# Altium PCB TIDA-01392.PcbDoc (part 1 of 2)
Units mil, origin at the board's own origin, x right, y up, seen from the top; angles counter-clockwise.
Board outline 1055.12 x 1877.5 mil, 6 copper layers (Layer 1 - Top Layer, Layer 2 - GND, Layer 3 - Signal, Layer 4 - Signal, Layer 5 - PWR, Layer 6 - Bottom Layer), stack 66.234 mil thick; 89 components, 55 nets, 288 pads, 112 vias.
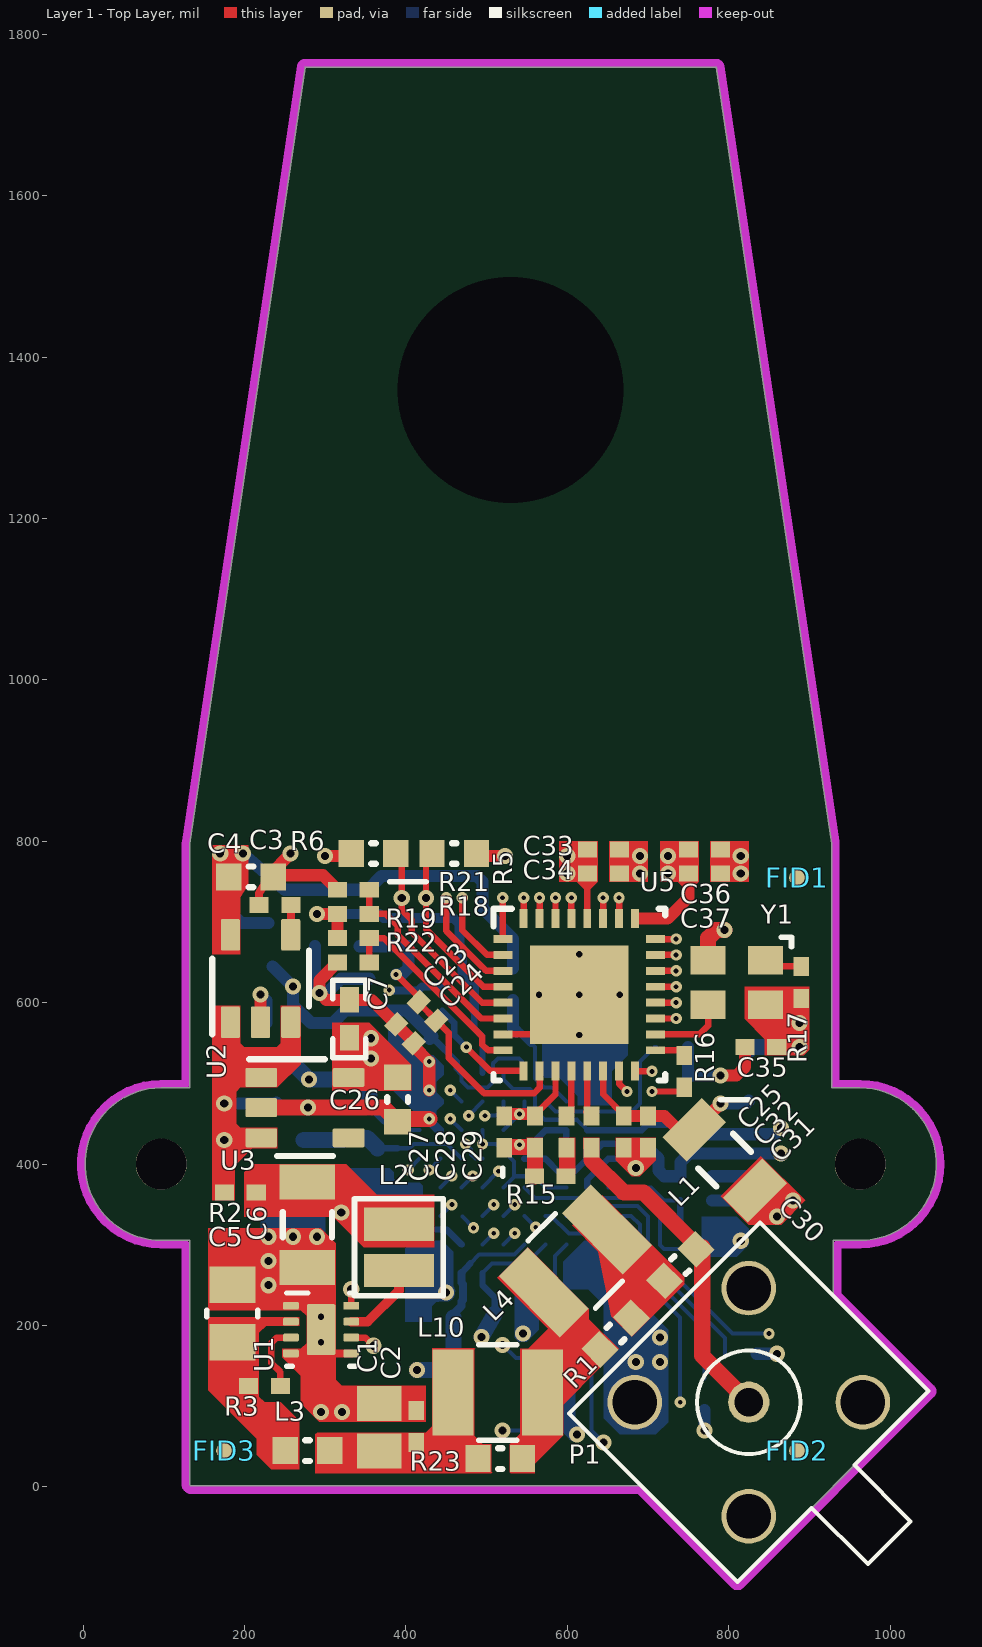
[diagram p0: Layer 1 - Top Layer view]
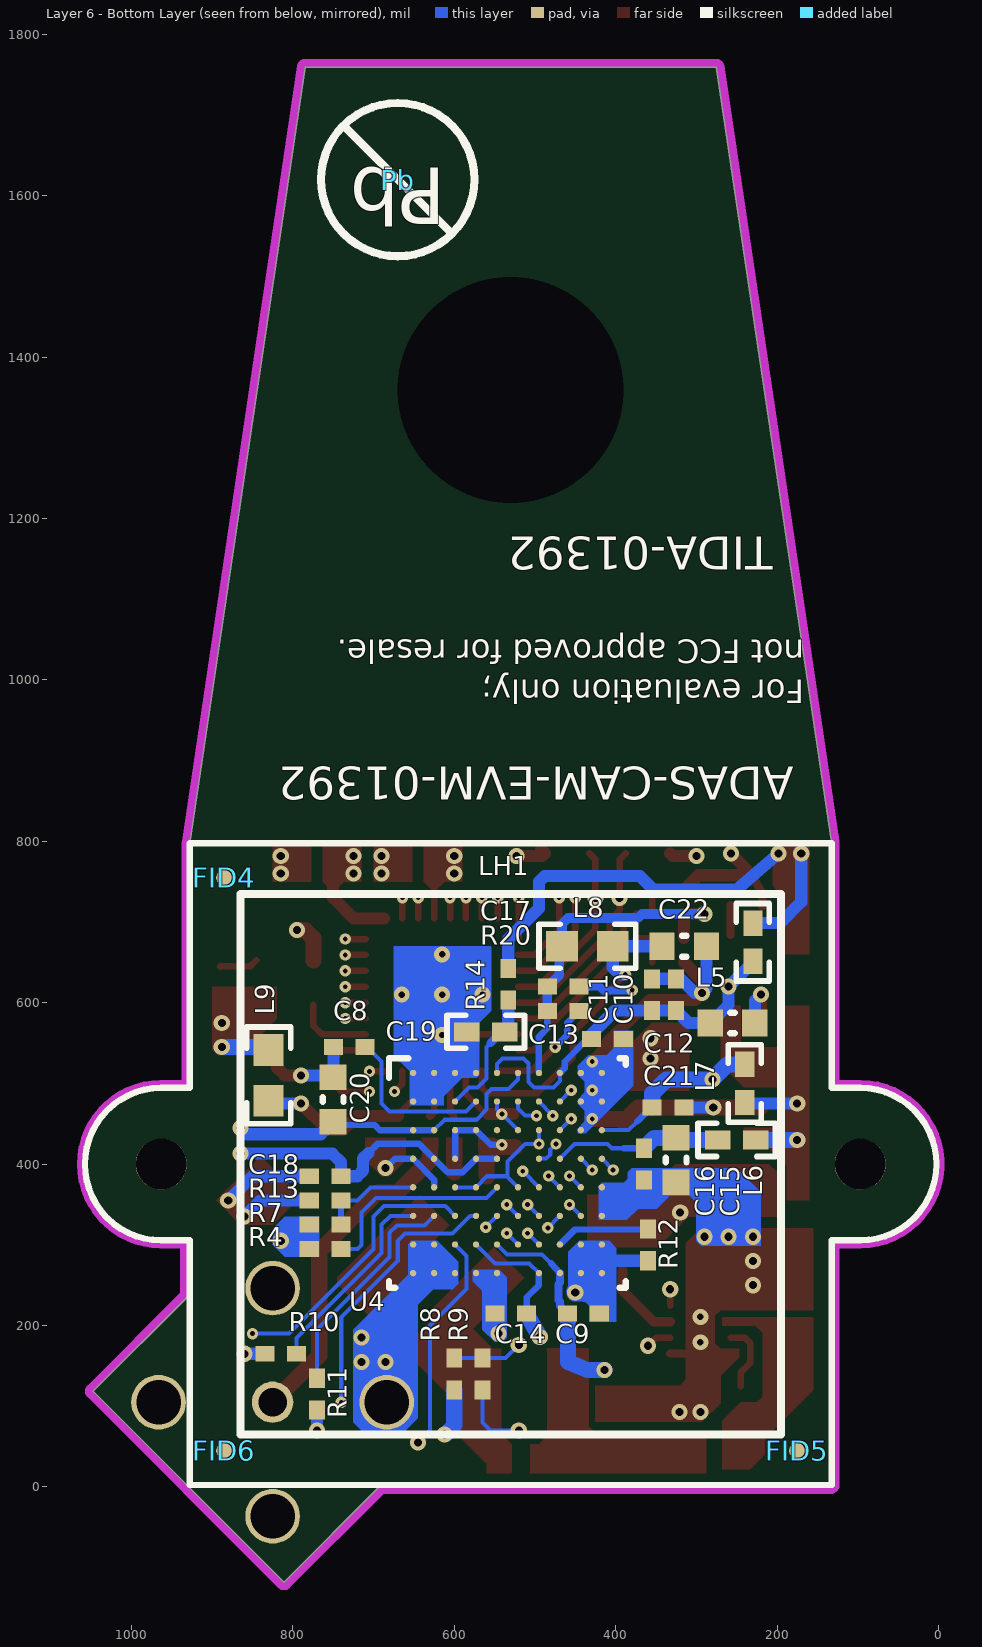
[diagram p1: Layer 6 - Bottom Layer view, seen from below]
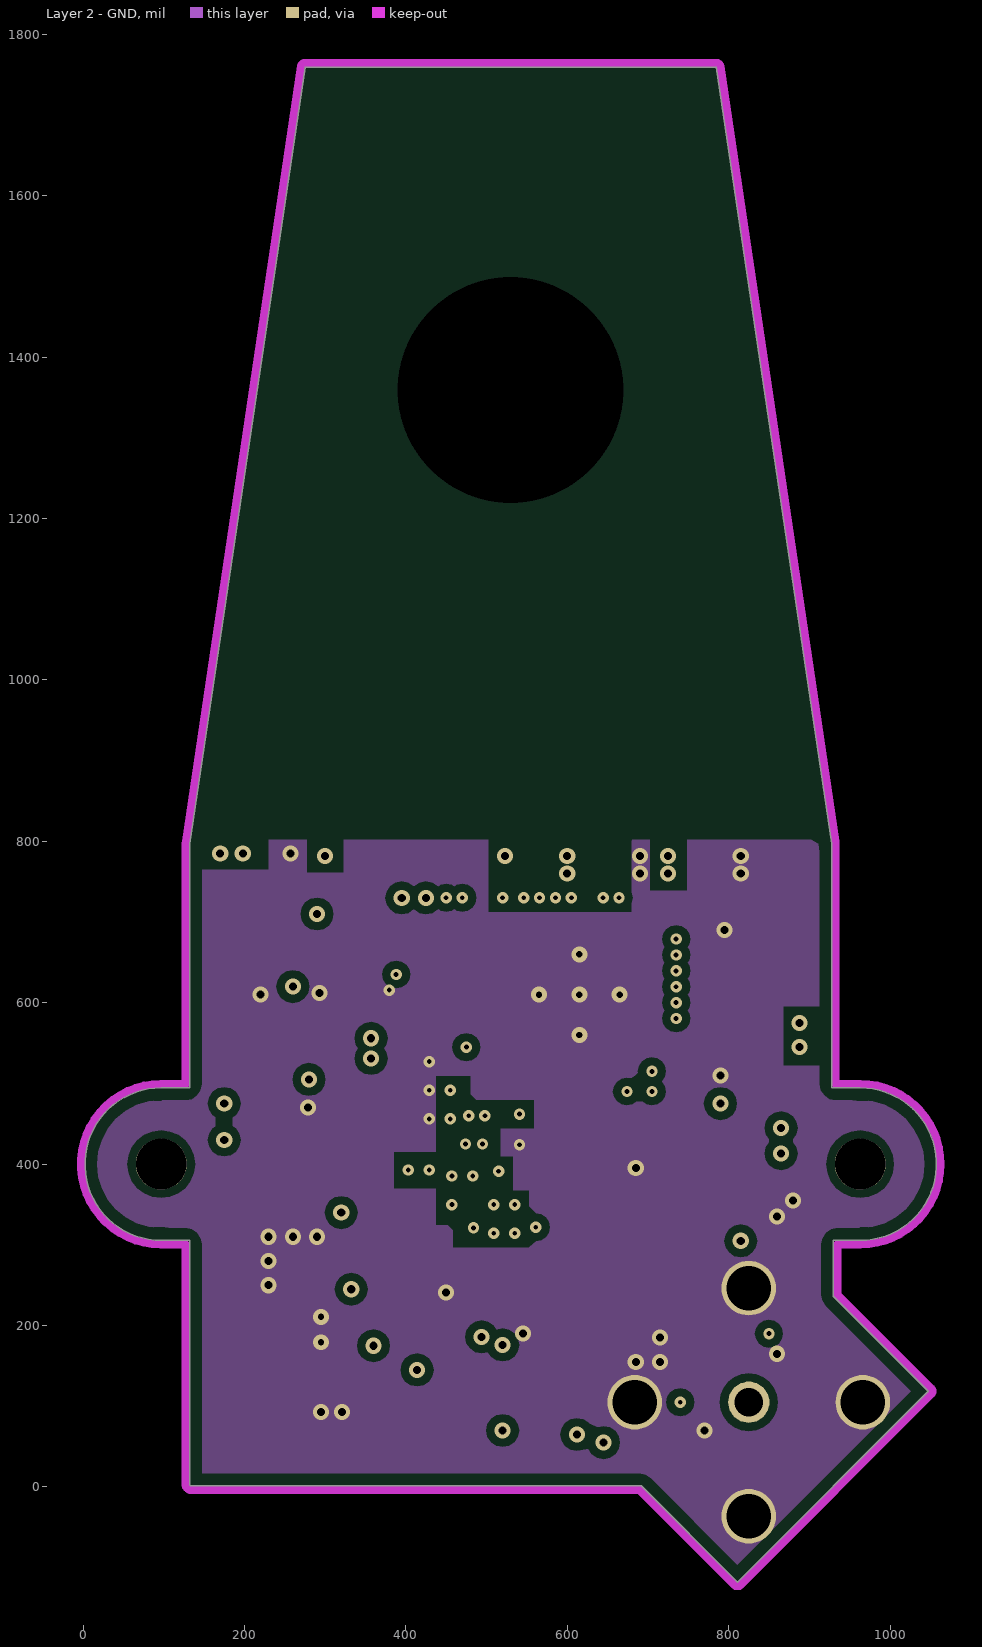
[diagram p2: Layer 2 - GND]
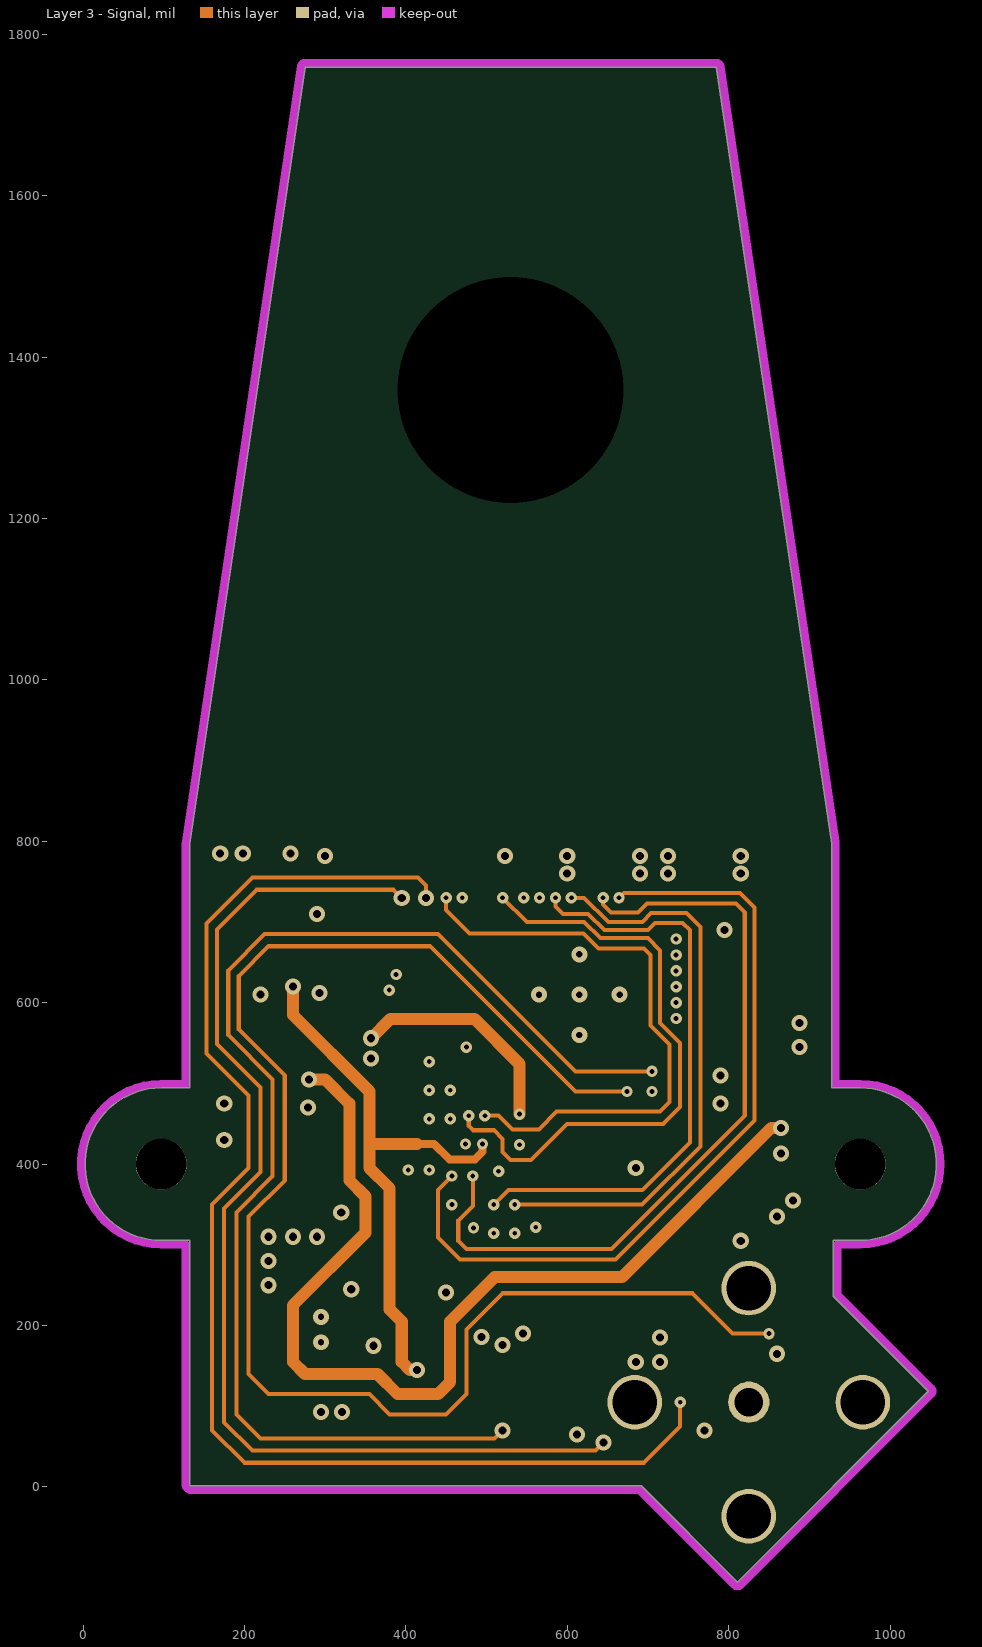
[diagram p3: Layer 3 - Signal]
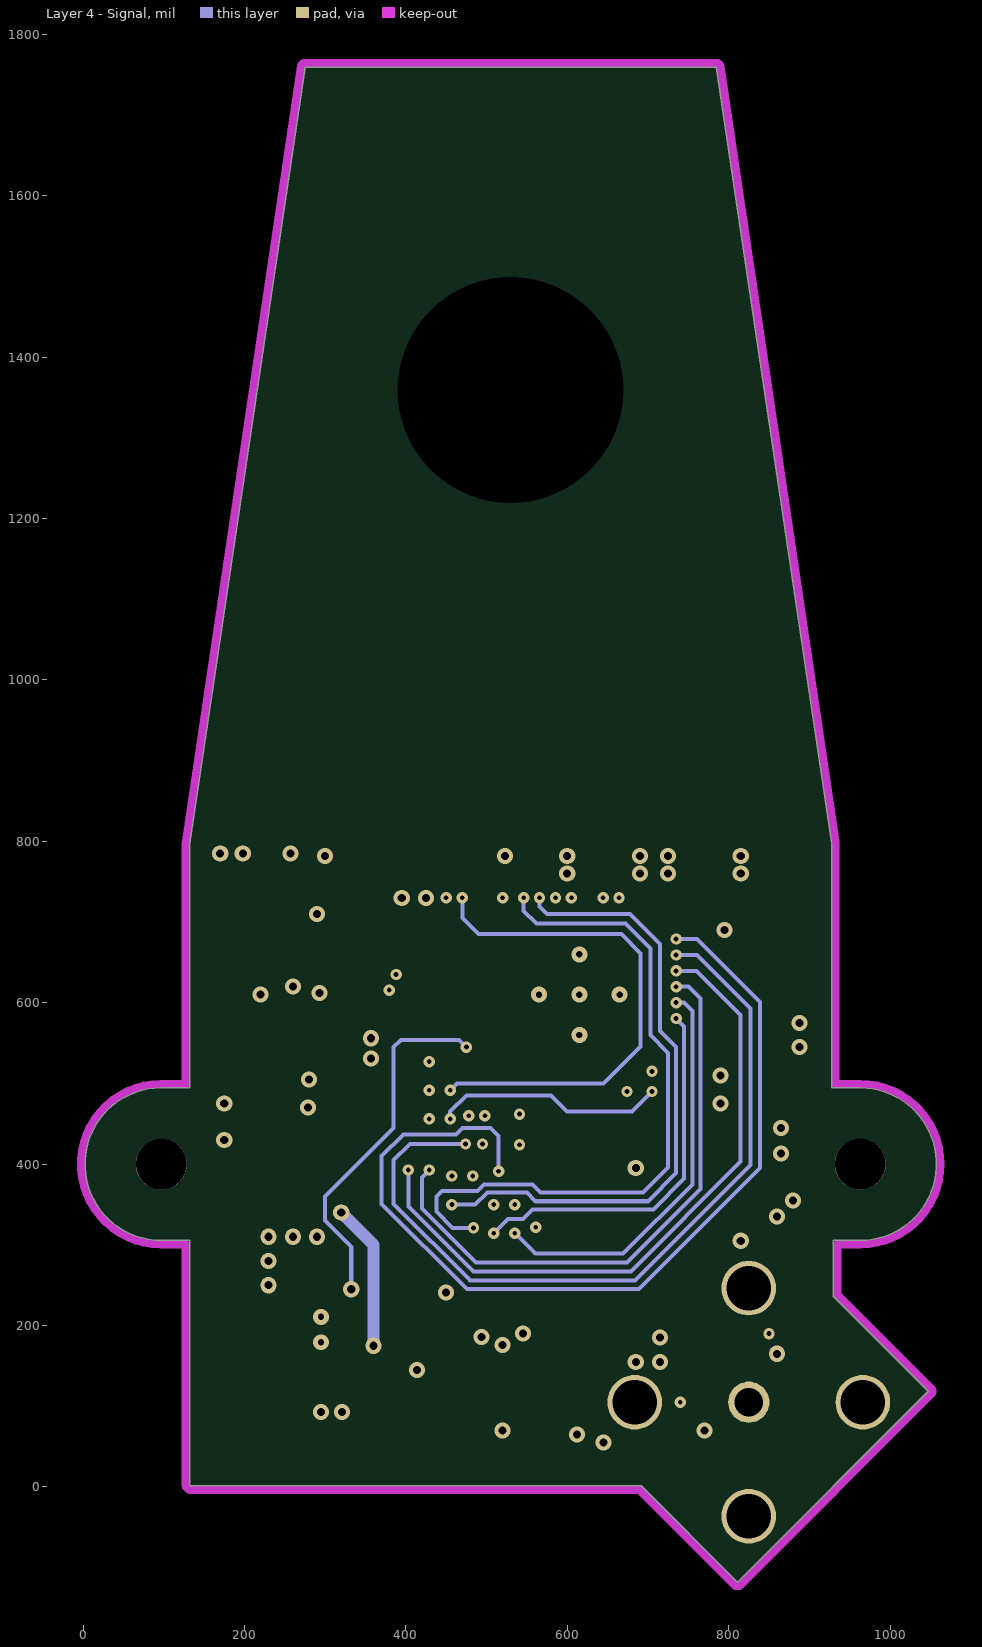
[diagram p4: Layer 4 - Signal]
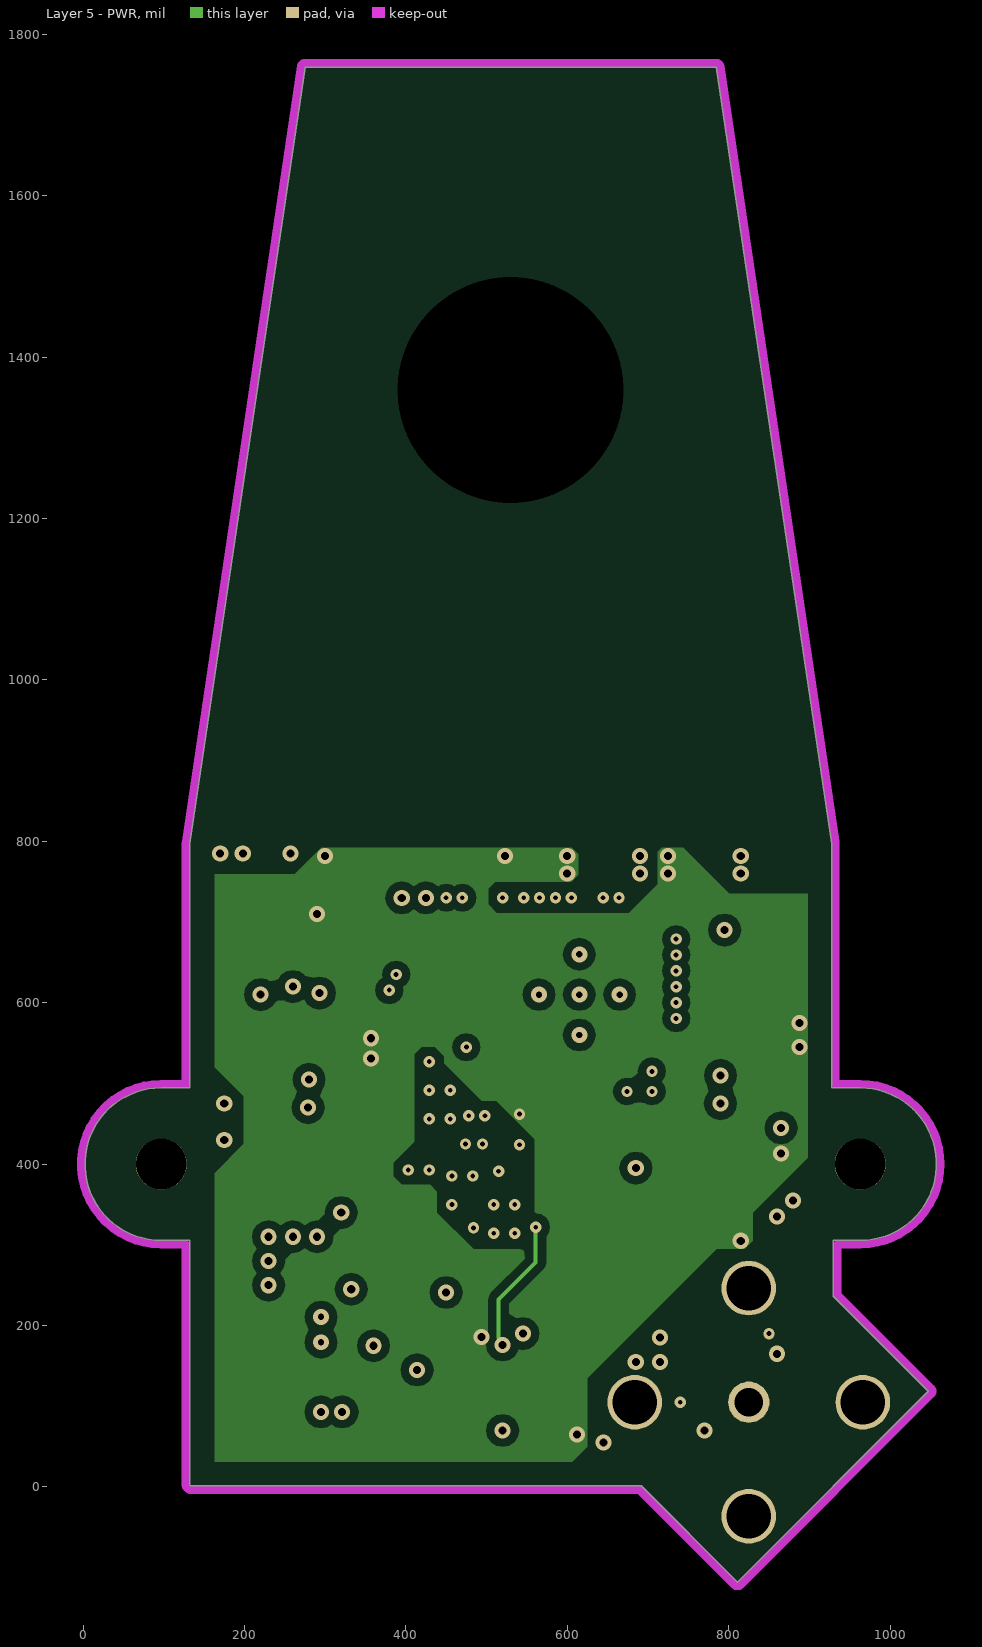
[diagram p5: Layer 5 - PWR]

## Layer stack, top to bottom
Top Solder: solder mask 0.4, Solder Resist, Dk 3.5
Layer 1 - Top Layer: signal copper 1.4
Dielectric 1: prepreg 12.6, 370HR, Dk 4.2
Layer 2 - GND: signal copper 1.4
Dielectric 2: core 8, 370HR, Dk 4.2
Layer 3 - Signal: signal copper 1.417
Dielectric 3: prepreg 16.6, 370HR, Dk 4.2
Layer 4 - Signal: signal copper 1.417
Dielectric 4: core 8, 370HR, Dk 4.2
Layer 5 - PWR: signal copper 1.4
Dielectric 5: prepreg 12.6, 370HR, Dk 4.2
Layer 6 - Bottom Layer: signal copper 1.4
Bottom Solder: solder mask 0.4, Solder Resist, Dk 3.5

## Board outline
96.93,305.51 132.36,305.51 132.36,2.36 133.35,1.37 691.63,1.37 811,-118 1047.5,118.5 929.63,236.37 929.63,305.51 963.07,305.51 ccw(c963.07,400) 963.07,494.49 927.64,494.49 927.64,797.64 927.64,797 784.75,1759.5 275.25,1759.5 132.36,797 132.36,797.64 132.36,494.49 96.93,494.49 ccw(c96.93,400)

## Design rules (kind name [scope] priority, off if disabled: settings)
AcuteAngle [All] p1 off: minimum=4.50000000000000E+0001 checktracksonly=FALSE
AssemblyTestPointUsage [All] p1: valid=2
Clearance Clearance_BoardEdge_MountingHoles [OnCopper and InComponentClass('Mounting Holes') vs IsKeepOut] p1 off: gap=30 ignorepadtopadclearanceinfootprint=FALSE except(0: Arc-Hole Track-Hole SMDPad-Hole THPad-Hole Via-Hole Fill-Hole Poly-Hole Region-Hole Text-Hole)
Clearance Clearance_BoardEdge_Poly [OnCopper and InPoly vs IsKeepOut] p2: gap=15 ignorepadtopadclearanceinfootprint=FALSE except(0: Arc-Hole Track-Hole SMDPad-Hole THPad-Hole Via-Hole Fill-Hole Poly-Hole Region-Hole Text-Hole)
Clearance Clearance_BoardEdge [OnCopper and Not InComponentClass('Logo') and not InComponentClass('FiducialMark') and not InRegion(1000,500,4000,800) and Not IsKeepout vs IsKeepOut and Not OnLayer('Keep-out Layer')] p3: gap=11 ignorepadtopadclearanceinfootprint=FALSE except(0: Arc-Hole Track-Hole SMDPad-Hole THPad-Hole Via-Hole Fill-Hole Poly-Hole Region-Hole Text-Hole)
Clearance Clearance_Poly [InPolygon] p4: gap=10 ignorepadtopadclearanceinfootprint=FALSE except(0: Arc-Hole Track-Hole SMDPad-Hole THPad-Hole Via-Hole Fill-Hole Poly-Hole Region-Hole Text-Hole)
Clearance [All] p5: gap=5 ignorepadtopadclearanceinfootprint=FALSE except(0: Arc-Hole Track-Hole SMDPad-Hole THPad-Hole Via-Hole Fill-Hole Poly-Hole Region-Hole Text-Hole)
ComponentClearance ComponentClearance_1 [issmtcomponent] p1: gap=0 collisioncheckmode=3 verticalgap=0 showdistances=FALSE
ComponentClearance ComponentClearance_Shunt [InComponentClass('Header') vs InComponentClass('Shunt')] p2: gap=0 collisioncheckmode=3 verticalgap=0 showdistances=FALSE
ComponentClearance ComponentClearance_Logo [InComponentClass('Logo')] p3: gap=0 collisioncheckmode=3 verticalgap=0 showdistances=FALSE
ComponentClearance ComponentClearance_ScrewToNut [(HasFootprint('NY PMS 440 0025 PH')) vs (HasFootprint('Keystone_1902C'))] p4: gap=5 collisioncheckmode=3 verticalgap=10 showdistances=FALSE
ComponentClearance ComponentClearance_MountingHoles [InComponentClass('Mounting Holes')] p5: gap=50 collisioncheckmode=3 verticalgap=50 showdistances=FALSE
ComponentClearance ComponentClearance_SmallPassives [HasFootprint('0201*') or HasFootprint('0402*') or HasFootprint('0508') or HasFootprint('0603*') or HasFootprint('0612') or HasFootprint('0805*') or HasFootprint('0815*') or HasFootprint('0830*') or HasFootprint('1206*') or HasFootprint('1210*') or HasFootprint('1808*') or HasFootprint('1812*') or HasFootprint('1825*') or HasFootprint('2010*') or HasFootprint('2220*') or HasFootprint('2225*') or HasFootprint('2512*') or HasFootprint('2728*') or HasFootprint('3518*') vs HasFootprint('0201*') or HasFootprint('0402*') or HasFootprint('0508') or HasFootprint('0603*') or HasFootprint('0612') or HasFootprint('0805*') or HasFootprint('0815*') or HasFootprint('0830*') or HasFootprint('1206*') or HasFootprint('1210*') or HasFootprint('1808*') or HasFootprint('1812*') or HasFootprint('1825*') or HasFootprint('2010*') or HasFootprint('2220*') or HasFootprint('2225*') or HasFootprint('2512*') or HasFootprint('2728*') or HasFootprint('3518*')] p6: gap=0 collisioncheckmode=3 verticalgap=0 showdistances=FALSE
ComponentClearance ComponentClearance_THtoSMT [IsThruComponent vs IsSMTComponent] p7: gap=0 collisioncheckmode=3 verticalgap=0 showdistances=FALSE
ComponentClearance ComponentClearance_THtoTH [IsThruComponent vs IsThruComponent] p8: gap=0 collisioncheckmode=3 verticalgap=0 showdistances=FALSE
ComponentClearance [All] p9: gap=0 collisioncheckmode=3 verticalgap=0 showdistances=FALSE
DiffPairsRouting [All] p1: maxlimit=100 minlimit=10 mostfreqgap=10 toplayer_minwidth=15 toplayer_maxwidth=15 toplayer_prefwidth=15 midlayer1_minwidth=15 midlayer1_maxwidth=15 midlayer1_prefwidth=15 midlayer2_minwidth=15 midlayer2_maxwidth=15 midlayer2_prefwidth=15 midlayer3_minwidth=15 midlayer3_maxwidth=15 midlayer3_prefwidth=15 midlayer4_minwidth=15 midlayer4_maxwidth=15 midlayer4_prefwidth=15 bottomlayer_minwidth=15 bottomlayer_maxwidth=15 bottomlayer_prefwidth=15 maxuncoupledlength=1000
FabricationTestPointUsage TestPointUsage [All] p1: valid=2 allowmultiple=FALSE
FabricationTestpoint Testpoint [All] p1: side=3 testpointundercomponent=TRUE minsize=40 maxsize=100 preferedsize=60 minholesize=0 maxholesize=40 preferedholesize=32 testpointgrid=1 allowsidetop=TRUE allowsidebottom=TRUE usegrid=TRUE gridtolerance=0.01
FanoutControl Fanout_LCC [IsLCC] p1: bgadir=Out bgaviamode=Centered fanoutstyle=Auto fanoutdirection=Alternating viagrid=1 // Fanout_LCC (Default Rule)
FanoutControl Fanout_BGA [IsBGA] p2: bgadir=Out bgaviamode=Centered fanoutstyle=Auto fanoutdirection=Alternating viagrid=1 // Fanout_BGA (Default Rule)
FanoutControl Fanout_Default [All] p4: bgadir=Out bgaviamode=Centered fanoutstyle=Auto fanoutdirection=Alternating viagrid=1 // Fanout_Default (Default Rule)
FanoutControl Fanout_Small [(CompPinCount < 5)] p5: bgadir=Out bgaviamode=Centered fanoutstyle=Auto fanoutdirection=OutThenIn viagrid=1 // Fanout_Small (Default Rule)
HoleSize [All] p1: absolutevalues=TRUE maxlimit=280 minlimit=6 maxpercent=80.000 minpercent=20.000
MinimumAnnularRing MinimumAnnularRing_ThermalPadVias [IsVia and InAnyComponent] p1: minimumring=5.91
MinimumAnnularRing [All] p2: minimumring=4
MinimumSolderMaskSliver MinimumSolderMaskSliver_Logo [InComponentClass('Logo') vs InComponentClass('Logo')] p1: minsoldermaskwidth=0.7
MinimumSolderMaskSliver [All] p2: minsoldermaskwidth=3.94
PlaneConnect [All] p1: planeconnectstyle=Relief reliefexpansion=10 reliefentries=4 reliefconductorwidth=10 reliefairgap=10
PolygonConnect [All] p1: connectstyle=Direct reliefconductorwidth=10 reliefentries=4 polygonreliefangle="90 Angle" airgapwidth=10
RoutingVias ThermalPadVias [IsVia and InAnyComponent] p1: holewidth=7.87 width=19.68 viastyle="Through Hole" minholewidth=7.87 minwidth=19.68 maxholewidth=12.99 maxwidth=23.62
RoutingVias [All] p2: holewidth=10 width=22 viastyle="Through Hole" minholewidth=6 minwidth=14 maxholewidth=40 maxwidth=65
SMDToCorner [All] p1: distance=25000
SilkToSilkClearance [All] p1: silktosilkclearance=0
SilkToSolderMaskClearance SilkscreenOverComponentPads [IsPad] p1: minsilkscreentomaskgap=0.2 clearancetoexposedcopper=TRUE
SolderMaskExpansion [All] p1: expansion=1
Width [All] p1: maxlimit=100 minlimit=5 preferedwidth=10 minimp=50.000000 maximp=50.000000 favimp=50.000000 checkconnectedcopper=TRUE
16 further rules are at their usual default settings.

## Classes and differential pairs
component class HDWR: Fcc FID1 FID2 FID3 FID4 FID5 FID6 LH1 Pb ZZ1 ZZ2 ZZ3
component class FiducialMark: FID1 FID2 FID3 FID4 FID5 FID6
component class AssemblyNote: ZZ1 ZZ2 ZZ3
component class Imager: C8 C9 C10 C11 C12 C13 C14 C15 C16 C17 C18 C19 C20 C21 L5 L6 L7 R4 R5 R6 R7 R8 R9 R10 R12 R13 R14 R23 U4
component class "Coax Connection and Power Supply": C1 C2 C3 C4 C5 C6 C7 L1 L2 L3 L4 L10 P1 R1 R2 R3 R23 U1 U2 U3
component class Serializer: C22 C23 C24 C25 C26 C27 C28 C29 C30 C31 C32 C33 C34 C35 C36 C37 L8 L9 R15 R16 R17 R18 R19 R20 R21 R22 U5 Y1

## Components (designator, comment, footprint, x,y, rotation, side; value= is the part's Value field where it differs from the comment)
C1 "CGA4J1X7R1E475M125AC" 0805L 367,74 r90 top value=4.7µF
C2 "C1005X7R1E104K050BB" 0402L#1 413,75 r90 top value=0.1µF
C3 "GRM155R71C104KA88D" 0402L#1 238,721 r180 top value=0.1uF
C4 "CL10B475KQ8NQND" 0603L#1 208,756 r0 top value=4.7uF
C5 "CL21B106KOQNNNE" 0805_140 185,215 r90 top value=10uF
C6 "GRM31CR71A226KE15L" 1206L 278,325 r270 top value=22uF
C7 "CL05B105KQ5NQNC" 0402 330,580 r90 top value=1.0µF
C8 "CL05B105KQ5NQNC" 0402L#1 730,545 r0 bottom value=1.0µF
C9 "CL05B105KQ5NQNC" 0402L#2 440,215 r0 bottom value=1.0µF
C10 "CL05B105KQ5NQNC" 0402L#2 325,610 r270 bottom value=1.0µF
C11 "CL05B105KQ5NQNC" 0402L#2 355,610 r270 bottom value=1.0µF
C12 "CL10B475KQ8NQNC" 0603L#1 255,575 r180 bottom value=4.7µF
C13 "C1005X7R1E104K050BB" 0402L#1 410,555 r180 bottom value=0.1µF
C14 "CL05B105KQ5NQNC" 0402L#2 530,215 r180 bottom value=1.0µF
C15 "CL10B475KQ8NQNC" 0603L#2 325,405 r90 bottom value=4.7µF
C16 "C1005X7R1E104K050BB" 0402L#1 365,400 r270 bottom value=0.1µF
C17 "CL05B105KQ5NQNC" 0402L#2 465,620 r0 bottom value=1.0µF
C18 "C1005X7R1E104K050BB" 0402L#1 760,385 r0 bottom value=0.1µF
C19 "GRM155R60J474KE19D" 0402 561,564 r0 bottom value=0.47uF
C20 "CL10B475KQ8NQNC" 0603L#2 750,480 r270 bottom value=4.7µF
C21 "C1005X7R1E104K050BB" 0402L#1 335,470 r180 bottom value=0.1µF
C22 "CL10B475KQ8NQNC" 0603L#1 315,670 r180 bottom value=4.7µF
C23 "GRM155R71C104KA88D" 0402L#1 402,587 r225 top value=0.1uF
C24 "GRM155R71C103KA01D" 0402L#1 424,564 r225 top value=0.01uF
C25 "C1005X7R1H104K050BE" 0402L#1 630,440 r90 top value=0.1uF
C26 "CL10B475KQ8NQNC" 0603L#1 390,480 r270 top value=4.7µF
C27 "GRM155R71C104KA88D" 0402L#1 522,440 r270 top value=0.1uF
C28 "GRM155R71C103KA01D" 0402L#1 560,440 r270 top value=0.01uF
C29 "C1005X7R1H473K050BB" 0402L#1 599,440 r90 top value=0.047uF
C30 "GRM31CR71A226KE15L" 1206L 795,405 r315 top value=22uF
C31 "GRM155R71C104KA88D" 0402L#1 700,440 r270 top value=0.1uF
C32 "GRM155R71C103KA01D" 0402L#1 670,440 r270 top value=0.01uF
C33 "GRM155R71C104KA88D" 0402L#1 645,790 r0 top value=0.1uF
C34 "GRM155R71C103KA01D" 0402L#1 645,760 r0 top value=0.01uF
C35 "GRM155R71C104KA88D" 0402L#1 840,545 r180 top value=0.1uF
C36 "GRM155R71C104KA88D" 0402L#1 770,790 r0 top value=0.1uF
C37 "GRM155R71C103KA01D" 0402L#1 770,760 r0 top value=0.01uF
Fcc "FCC disclaimer" FCC_disclaimer 1138,576 r90 top
FID1 "Fiducial" Fiducial10-20 885,755 r0 top
FID2 "Fiducial" Fiducial10-20 885,45 r0 top
FID3 "Fiducial" Fiducial10-20 175,45 r0 top
FID4 "Fiducial" Fiducial10-20 885,755 r90 bottom
FID5 "Fiducial" Fiducial10-20 175,45 r90 bottom
FID6 "Fiducial" Fiducial10-20 885,45 r90 bottom
L1 "BLM18AG102SN1D" 0603L#1 740,275 r45 top value="1000 ohm"
L2 "XPL2010-472MLB" XPL2010 391.5,297 r90 top value=4.7uH
L3 "BLM18AG102SN1D" 0603L#1 278,45 r180 top value="1000 ohm"
L4 "CBC3225T4R7MR" CBC3225 610,280 r225 top value=4.7uH
L5 "BLM15AX102SN1D" 0402 230,675 r270 bottom value="1000 ohm"
L6 "BLM15AX102SN1D" 0402 250,430 r0 bottom value="1000 ohm"
L7 "BLM15AX102SN1D" 0402 240,500 r90 bottom value="1000 ohm"
L8 "BLM18KG601SN1D" 0603 435,670 r180 bottom value="600 ohm"
L9 "BLM18KG601SN1D" 0603 830,510 r270 bottom value="600 ohm"
L10 "CBC3225T101MR" CBC3225 514,117 r180 top value=100uH
LH1 "CMT821" CMT821 530,400 r180 bottom locked
P1 "59S10H-40ML5-Y" 59S10H-40ML5-Y 825,105 r315 top
Pb "Pb-Free Symbol" Pb-Free_Overlay_Medium 670,1620 r0 bottom
R1 "CRCW06031K00JNEA" 0603L#1 660,190 r45 top value=1.0k
R2 "CRCW04020000Z0ED" 0402L#1 195,365 r0 top value=0
R3 "CRCW040210K0JNED" 0402L#1 225,125 r180 top value=10k
R4 "CRCW040210K0JNED" 0402L#1 760,295 r0 bottom value=10k
R5 "CRCW06033K30JNEA" 0603L#1 460,785 r0 top value=3.3k
R6 "CRCW06033K30JNEA" 0603L#1 360,785 r180 top value=3.3k
R7 "CRCW040210K0DHEDP" 0402L#1 760,325 r0 bottom value=10.0k
R8 "CRCW040210K0JNED" 0402L#1 600,140 r270 bottom value=10k
R9 "CRCW04020000Z0ED" 0402L#1 565,140 r270 bottom value=0
R10 "CRCW040210K0JNED" 0402L#1 815,165 r180 bottom value=10k
R11 "CRCW040210K0JNED" 0402L#1 770,115 r90 bottom value=10k
R12 "CRCW040210K0JNED" 0402L#1 360,300 r90 bottom value=10k
R13 "CRCW040210K0JNED" 0402L#1 760,355 r180 bottom value=10k
R14 "CRCW04020000Z0ED" 0402L#1 533,623 r90 bottom value=0
R15 "CRCW040249R9FKED" 0402L#1 579,385 r180 top value=49.9
R16 "CRCW040233R0JNED" 0402L#1 745,515 r270 top value=33
R17 "CRCW040210K0JNED" 0402L#1 890,625 r270 top value=10k
R18 "CRCW040210K0JNED" 0402L#1 335,710 r180 top value=10k
R19 "CRCW040210K0JNED" 0402L#1 335,680 r180 top value=10k
R20 "CRCW040210K0JNED" 0402L#1 465,590 r0 bottom value=10k
R21 "CRCW04020000Z0ED" 0402L#1 335,740 r0 top value=0
R22 "" 0402L#1 335,650 r0 top value=4.75k
R23 "CRCW06031K00JNEA" 0603L#1 517,35 r0 top value=1.0k
U1 "TPS62172QDSGRQ1" DSG0008A 295,195 r0 top
U2 "TPS79915QDDCRQ1" DDC0005A_N 220,630 r90 top
U3 "TLV70018QDDCRQ1" DDC0005A_N 275,470 r0 top
U4 "OV10640-N79Y-1C-Z" OVT_10640_aCSP 534,389 r180 bottom locked
U5 "DS90UB933QSQE/NOPB" RTV0032A 615,610 r0 top
Y1 "ECS-2018-480-BN" ECS_2018 810,625 r270 top
ZZ1 "These assemblies are ESD sensitive, ESD precautions shall be observed." AssemblyNote 200,2100 r0 top
ZZ2 "These assemblies must be clean and free from flux and all contaminants. Use of no clean flux is not acceptable." AssemblyNote 200,2000 r0 top
ZZ3 "These assemblies must comply with workmanship standards IPC-A-610 Class 2, unless otherwise specified." AssemblyNote 200,1900 r0 top

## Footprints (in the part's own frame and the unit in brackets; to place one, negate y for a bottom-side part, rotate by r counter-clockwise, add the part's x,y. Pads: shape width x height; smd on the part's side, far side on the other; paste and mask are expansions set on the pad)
59S10H-40ML5-Y [mm] "Rosenberger Straight Plug"
  round 1.3 hole 0.9 mask+0: 1(0,0)
  round 1.72 hole 1.4 mask+0: 2(-2.54,2.54) 3(-2.54,-2.54) 4(2.54,-2.54) 5(2.54,2.54)
  silkscreen extent -3.75,-4.25 6.25,4.25
0402 [mm] "0402 from SM-752 data"
  rect 0.8x0.6 smd: 1(-0.6,0) 2(0.6,0)
  silkscreen extent -1.22,-0.52 1.22,0.52, body extent -0.55,-0.3 0.55,0.3, height 0.6
0402L#1 [mm] "0402 from SM-752 data"
  rect 0.6x0.5 smd: 1(-0.5,0) 2(0.5,0)
  body extent -0.55,-0.3 0.55,0.3, height 0.6
0402L#2 [mm] "0402 from SM-752 data"
  rect 0.6x0.5 smd: 1(0.5,0) 2(-0.5,0)
  body extent -0.55,-0.3 0.55,0.3, height 0.6
0603 [mm] "0603 from SM-752 data"
  rect 1x0.95 smd: 1(-0.8,0) 2(0.8,0)
  silkscreen extent -1.52,-0.69 1.52,0.69, body extent -0.87,-0.47 0.87,0.47, height 0.85
0603L#1 [mm] "0603 from SM-752 data"
  rect 0.8x0.85 smd: 1(-0.7,0) 2(0.7,0)
  silkscreen extent -0.07,-0.33 0.07,0.33, body extent -0.87,-0.47 0.87,0.47, height 1
0603L#2 [mm] "0603 from SM-752 data"
  rect 0.8x0.85 smd: 1(0.7,0) 2(-0.7,0)
  silkscreen extent -0.07,-0.33 0.07,0.33, body extent -0.87,-0.47 0.87,0.47, height 0.85
0805_140 [mm] "0805 / 1.4mm height"
  rect 1.15x1.45 smd: 1(-0.9,0) 2(0.9,0)
  silkscreen extent -0.1,-0.8 0.1,0.8, body extent -1.1,-0.72 1.1,0.72, height 1.4
0805L [mm] "0805 from SM-752 data"
  rect 1.1x1.4 smd: 1(-0.75,0) 2(0.75,0)
  body extent -1.1,-0.72 1.1,0.72, height 1.1
1206L [mm] "1206 from SM-752 data"
  rect 1.1x1.75 smd: 1(-1.35,0) 2(1.35,0)
  silkscreen extent -0.4,-0.77 0.4,0.77, body extent -1.7,-0.9 1.7,0.9, height 1.35
AssemblyNote [mil] "Assembly Note"
CBC3225 [mm] "TAIYO YUDEN, IPC nominal footprint."
  rect 1.29x2.72 smd: 1(-1.405,0) 2(1.405,0)
  silkscreen extent -0.6,-1.5 0.6,1.5, body extent -1.7,-1.35 1.7,1.35, height 2.7
CMT821 [mm] "SUNEX Lens Holder"
  round 1.6 hole 1.6 unplated paste+0: MT1(-11,0) MT2(11,0)
  M6 Assembly Bottom keep-out lines w0.2: 8.5,-8.5 -8.5,-8.5 -8.5,8.5 8.5,8.5 8.5,-8.5
  silkscreen extent -13.4,-10.1 13.4,10.1
DDC0005A_N [mm]
  rrect17% 1x0.6 smd: 1(-1.375,0.95) 2(-1.375,0) 3(-1.375,-0.95) 4(1.375,-0.95) 5(1.375,0.95)
  silkscreen extent -1.75,-1.52 0.88,1.53, body extent -1.41,-1.45 1.41,1.45, height 1.1
DSG0008A [mm] "SON, 8-Leads, Body 2x2mm, Pitch 0.5mm, Thermal Pad 1.6x0.9mm, TI Recommended"
  rrect40% 0.5x0.25 smd: 1(-0.95,0.75) 2(-0.95,0.25) 3(-0.95,-0.25) 4(-0.95,-0.75) 5(0.95,-0.75) 6(0.95,-0.25) 7(0.95,0.25) 8(0.95,0.75)
  rrect11% 0.9x1.6 smd paste-0.45: 9(0,0)
  silkscreen extent -1.07,-1.15 1.07,1.15, body extent -1.05,-1.05 1.05,1.05, height 0.8
ECS_2018 [mm] "ECS"
  rect 0.9x1.1 smd: 1(-0.7,0.9) 2(-0.7,-0.9) 3(0.7,-0.9) 4(0.7,0.9)
  silkscreen extent -1.43,1.4 -1.12,1.73, body extent -1.05,-1.3 1.05,1.3, height 0.9
FCC_disclaimer [mil]
Fiducial10-20 [mil]
  round 20 smd paste-19.68 mask+19.68: 1(0,0)
OVT_10640_aCSP [mm] "BGA, 78-Leads, Body 7.19x7.43mmx0.82mm, Pitch 0.66mm"
  round 0.2 smd: A1(-2.97,3.15) A2(-2.31,3.15) A3(-1.65,3.15) A4(-0.99,3.15) A5(-0.33,3.15) A6(0.33,3.15) A7(0.99,3.15) A8(1.65,3.15) A9(2.31,3.15) A10(2.97,3.15) B1(-2.97,2.25) B2(-2.31,2.25) B3(-1.65,2.25) B4(-0.99,2.25) B5(-0.33,2.25) B6(0.33,2.25) B7(0.99,2.25) B8(1.65,2.25) B9(2.31,2.25) B10(2.97,2.25) C1(-2.97,1.35) C2(-2.31,1.35) C3(-1.65,1.35) C4(-0.99,1.35) C5(-0.33,1.35) C6(0.33,1.35) C7(0.99,1.35) C8(1.65,1.35) C9(2.31,1.35) C10(2.97,1.35) D1(-2.97,0.45) D2(-2.31,0.45) D3(-1.65,0.45) D4(-0.99,0.45) D5(-0.33,0.45) D7(0.99,0.45) D8(1.65,0.45) D9(2.31,0.45) D10(2.97,0.45) E1(-2.97,-0.45) E2(-2.31,-0.45) E3(-1.65,-0.45) E4(-0.99,-0.45) E5(-0.33,-0.45) E6(0.33,-0.45) E7(0.99,-0.45) E8(1.65,-0.45) E9(2.31,-0.45) E10(2.97,-0.45) F1(-2.97,-1.35) F2(-2.31,-1.35) F3(-1.65,-1.35) F4(-0.99,-1.35) F5(-0.33,-1.35) F6(0.33,-1.35) F7(0.99,-1.35) F8(1.65,-1.35) F9(2.31,-1.35) F10(2.97,-1.35) G1(-2.97,-2.25) G2(-2.31,-2.25) G3(-1.65,-2.25) G4(-0.99,-2.25) G5(-0.33,-2.25) G6(0.33,-2.25) G7(0.99,-2.25) G8(1.65,-2.25) G9(2.31,-2.25) G10(2.97,-2.25) H1(-2.97,-3.15) H2(-2.31,-3.15) H3(-1.65,-3.15) H4(-0.99,-3.15) H5(-0.33,-3.15) H7(0.99,-3.15) H8(1.65,-3.15) H9(2.31,-3.15) H10(2.97,-3.15)
  silkscreen extent -3.73,-3.61 3.73,3.61, body extent -3.73,-3.61 3.73,3.61, height 0.83
Pb-Free_Overlay_Medium [mil]
  silkscreen extent -95,-95 95,95
RTV0032A [mm] "QFN, 32-Leads, Body 5x5mm, Pitch 0.5mm"
  rect 0.6x0.25 smd: 1(-2.4,1.75) 2(-2.4,1.25) 3(-2.4,0.75) 4(-2.4,0.25) 5(-2.4,-0.25) 6(-2.4,-0.75) 7(-2.4,-1.25) 8(-2.4,-1.75) 17(2.4,-1.75) 18(2.4,-1.25) 19(2.4,-0.75) 20(2.4,-0.25) 21(2.4,0.25) 22(2.4,0.75) 23(2.4,1.25) 24(2.4,1.75)
  rect 0.25x0.6 smd: 9(-1.75,-2.4) 10(-1.25,-2.4) 11(-0.75,-2.4) 12(-0.25,-2.4) 13(0.25,-2.4) 14(0.75,-2.4) 15(1.25,-2.4) 16(1.75,-2.4) 25(1.75,2.4) 26(1.25,2.4) 27(0.75,2.4) 28(0.25,2.4) 29(-0.25,2.4) 30(-0.75,2.4) 31(-1.25,2.4) 32(-1.75,2.4)
  rect 3.1x3.1 smd paste-1.55: 33(0,0)
  silkscreen extent -2.7,-2.7 2.7,2.7, body extent -2.55,-2.55 2.55,2.55, height 0.81
XPL2010 [mm] "Coilcraft recommended land pattern Document 646-2 Revised 3/28/11"
  rect 1.04x2.2 smd: 1(-0.725,0) 2(0.725,0)
  silkscreen extent -1.52,-1.4 1.52,1.4, body extent -1.05,-1.1 1.05,1.1, height 1

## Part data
C1: library part C2012X7R1E474K, "CAP, CERM, 4.7uF, 25V, +/-20%, X7R, 0805", Manufacturer="TDK Corporation", Operating Temperature="-55°C ~ 125°C", Ratings=AEC-Q200, Supplier Part Number 1=445-12761-1-ND, TempCo=X7R, Tolerance_%=±20%
C2 C13 C16 C18 C21: library part C1005X7R1E103K, "CAP, CERM, 0.1uF, 25V, +/-10%, X7R, 0402", Manufacturer="TDK Corporation", Operating Temperature="-55°C ~ 125°C", Ratings=-, Supplier Part Number 1=445-7348-1-ND, TempCo=X7R, Tolerance_%=±10%
C3: "CAP, CERM, 0.1 µF, 16 V, +/- 10%, X7R, 0402", Cap_Case=0402, Manufacturer=MuRata, Supplier Part Number 1=490-3261-1-ND, TempCo=X7R, Tolerance_%=10, Value1=Unknown, Value2=16V, ValueDisplayed=0.1µF
C4: "CAP, CERM, 4.7 µF, 6.3 V, +/- 10%, X7R, 0603", Cap_Case=0603, Manufacturer=Samsung, Supplier Part Number 1=1276-2087-1-ND, TempCo=X7R, Tolerance_%=10, Value1=Unknown, Value2=6.3V, ValueDisplayed=4.7µF
C5: "CAP, CERM, 10 µF, 16 V, +/- 10%, X7R, 0805_140", Cap_Case=0805, Manufacturer="Samsung Electro-Mechanics", TempCo=X7R, Tolerance_%=10, Value1=Unknown, Value2=16V, ValueDisplayed=10µF
C6 C30: "CAP, CERM, 22uF, 10V, +/-10%, X7R, 1206", Cap_Case=1206, Manufacturer=MuRata, Supplier Part Number 1=490-5309-1-ND, TempCo=X7R, Tolerance_%=10, Value1=Unknown, Value2=10V, ValueDisplayed=22µF
C7 C8 C9 C10 C11 C14 C17: library part Capacitor, "CAP CER 1UF 6.3V 10% X7R 0402", Alternate Manufacturer=-, Manufacturer="Samsung Electro-Mechanics America, Inc", Operating Temperature="-55°C ~ 125°C", Supplier Part Number 1=1276-1513-1-ND, TempCo=X7R, Tolerance_%=±10%
C12 C15 C20 C22 C26: library part Capacitor, "CAP CER 4.7UF 6.3V 10% X7R 0603", Alternate Manufacturer=-, Manufacturer="Samsung Electro-Mechanics America, Inc", Operating Temperature="-55°C ~ 125°C", Supplier Part Number 1=1276-2087-1-ND, TempCo=X7R, Tolerance_%=±10%
C19: "CAP, CERM, 0.47 µF, 6.3 V, +/- 10%, X5R, 0402", Cap_Case=0402, Manufacturer=MuRata, Supplier Part Number 1=490-3266-1-ND, TempCo=X5R, Tolerance_%=10, Value1=Unknown, Value2=6.3V, ValueDisplayed=0.47µF
C23 C27 C31 C33 C35 C36: "CAP, CERM, 0.1uF, 16V, +/-10%, X7R, 0402", Cap_Case=0402, Manufacturer=MuRata, Supplier Part Number 1=490-3261-1-ND, TempCo=X7R, Tolerance_%=10, Value1=Unknown, Value2=16V, ValueDisplayed=0.1µF
C24 C28 C32 C34 C37: "CAP, CERM, 0.01uF, 16V, +/-10%, X7R, 0402", Cap_Case=0402, Manufacturer=MuRata, Supplier Part Number 1=490-1313-1-ND, TempCo=X7R, Tolerance_%=10, Value1=Unknown, Value2=16V, ValueDisplayed=0.01µF
C25: library part C1005X7R1H104K, "CAP, CERM, 0.1uF, 50V, +/-10%, C0G/NP0, 0402", Cap_Case=0402, Manufacturer=TDK, Supplier Part Number 1=445-5932-1-ND, TempCo=C0G/NP0, Tolerance_%=10, Value1=Unknown, Value2=50V, ValueDisplayed=0.1µF
C29: "CAP, CERM, 0.047 µF, 50 V, +/- 10%, X7R, 0402", Cap_Case=0402, Manufacturer=TDK, Supplier Part Number 1=445-7336-1-ND, TempCo=X7R, Tolerance_%=10, Value1="0.06407 ohm", Value2=50V, ValueDisplayed=0.047µF
Fcc: library part FCC_disclaimer, "FCC_disclaimer"
FID1 FID2 FID3 FID4 FID5 FID6: "Fiducial mark.  There is nothing to buy or mount.", Manufacturer=N/A
L1 L3: "Ferrite Bead, 1000 ohm @ 100 MHz, 0.4 A, 0603", Manufacturer=MuRata, Supplier Part Number 1=490-1015-1-ND, Value1="0.5 ohm", Value2=0.4A
L2: "Inductor, Shielded, Composite, 4.7 µH, 0.85 A, 0.34 ohm, SMD", Manufacturer=Coilcraft, Value1="0.34 ohm", Value2=0.85A, ValueDisplayed=4.7µH
L4: "Inductor, Wirewound, 4.7 µH, 1.01 A, 0.1 ohm, SMD", Manufacturer="Taiyo Yuden", Supplier Part Number 1=587-1624-1-ND, Value1="0.1 ohm", Value2=1.01A, ValueDisplayed=4.7µH
L5 L6 L7: "Ferrite Bead, 1000 ohm @ 100 MHz, 0.35 A, 0402", Manufacturer=MuRata, Supplier Part Number 1=490-5442-1-ND, Value1="0.49 ohm", Value2=0.35A
L8 L9: "1.3A Ferrite Bead, 600 ohm @ 100MHz, SMD", Manufacturer=MuRata, Supplier Part Number 1=490-5258-1-ND, Value1="0.15 ohm", Value2=1.3A
L10: "Inductor, Wirewound, 100 µH, 0.27 A, 1.4 ohm, SMD", Manufacturer="Taiyo Yuden", Supplier Part Number 1=587-1628-1-ND, Value1="1.4 ohm", Value2=0.27A, ValueDisplayed=100µH
LH1: "Sunex Lens Holder", Manufacturer="Sunex Inc."
P1: "Straight Plug PCB", Alternate Manufacturer=-, Manufacturer=Rosenberger
Pb: library part Pb-Free
R1 R23: "RES, 1.0 k, 5%, 0.1 W, 0603", Manufacturer=Vishay-Dale, Power_W=0.1, Supplier Part Number 1=541-1.0KGCT-ND, TempCo="200 ppm/C", Tolerance_%=5, Value1=5%, Value2=0.1W, Value_Code=1k00, ValueDisplayed=1.0k
R2 R9 R14 R21: "RES, 0 ohm, 5%, 0.063W, 0402", Manufacturer=Vishay-Dale, Power_W=0.063, Supplier Part Number 1=541-0.0JCT-ND, TempCo="200 ppm/C", Tolerance_%=5, Value1=5%, Value2=0.063W, Value_Code=0000
R3 R4 R8 R10 R11 R12 R13 R17 R18 R19 R20: "RES, 10k ohm, 5%, 0.063W, 0402", Manufacturer=Vishay-Dale, Power_W=0.063, Supplier Part Number 1=71-CRCW0402J-10K-E3, TempCo="200 ppm/C", Tolerance_%=5, Value1=5%, Value2=0.063W, Value_Code=10k0
R5 R6: "RES, 3.3k ohm, 5%, 0.1W, 0603", Manufacturer=Vishay-Dale, Power_W=0.1, Supplier Part Number 1=541-3.3KGCT-ND, TempCo="200 ppm/C", Tolerance_%=5, Value1=5%, Value2=0.1W, Value_Code=3k30
R7: "RES, 10.0 k, 0.5%, 0.063 W, 0402", Manufacturer=Vishay-Dale, Power_W=0.063, Supplier Part Number 1=541-10KAVCT-ND, TempCo="50 ppm/C", Tolerance_%=0.5, Value1=0.5%, Value2=0.063W, Value_Code=10k0, ValueDisplayed=10.0k
R15: "RES, 49.9 ohm, 1%, 0.063W, 0402", Manufacturer=Vishay-Dale, Power_W=0.063, Supplier Part Number 1=541-49.9LCT-ND, TempCo="100 ppm/C", Tolerance_%=1, Value1=1%, Value2=0.063W, Value_Code=49R9
R16: "RES, 33 ohm, 5%, 0.063W, 0402", Manufacturer=Vishay-Dale, Power_W=0.063, Supplier Part Number 1=541-33JCT-ND, TempCo="200 ppm/C", Tolerance_%=5, Value1=5%, Value2=0.063W, Value_Code=33R0
R22: library part CRCW04024K75FKED, "RES, 4.75k ohm, 1%, 0.063W, 0402", Manufacturer=Vishay-Dale, Power_W=0.063, Supplier Part Number 1=541-4.75KLCT-ND, TempCo="100 ppm/C", Tolerance_%=1, Value1=1%, Value2=0.063W, Value_Code=4k75
U1: "3-V to17-V 0.5-A Step-Down Converters with DCS-Control™, DSG0008A (WSON-8)", Alternate Manufacturer="Texas Instruments", Alternate PartNumber=TPS62172QDSGTQ1
U2: "Single Output High PSRR LDO, 200 mA, Fixed 1.5 V Output, 2.7 to 6.5 V Input, with Low IQ, 5-pin SOT (DDC), -40 to 125 degC, Green (RoHS & no Sb/Br)", Alternate Manufacturer="Texas Instruments", Alternate PartNumber=Equivalent, Rating=Automotive, Supplier Part Number 1=296-25740-2-ND
U3: "Single Output Automotive LDO, 300 mA, Fixed 1.8 V Output, 2 to 5.5 V Input, with Low IQ, 5-pin SOT (DDC), -40 to 125 degC, Green (RoHS & no Sb/Br)", Alternate Manufacturer="Texas Instruments", Alternate PartNumber=Equivalent, Supplier Part Number 1=TLV70018QDDCRQ1-ND
U4: "1/2.56\" color CMOS 1.3 megapixel HDR HD image sensor, BGA78", Manufacturer="OmniVision Technologies"
U5: "10-100MHz 10/12- Bit DC-Balanced FPD-Link III Serializer and Deserializer with Bidirectional Control Channel, RTV0032A (WQFN-32)", Alternate Manufacturer="Texas Instruments"
Y1: "XO, 48.000MHz, 1.8V, SMD", Frequency=48.000MHz, Frequency Stability=±50ppm, Manufacturer="ECS Inc.", Supplier Part Number 1=XC1415DKR-ND
ZZ1 ZZ2 ZZ3: library part AssemblyNote, Alternate Manufacturer=-

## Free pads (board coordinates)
  round 60 hole 280 unplated: 0(530,1359.5)

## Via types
v1: diameter 20, hole 10, Layer 1 - Top Layer to Layer 6 - Bottom Layer, tented both sides, 57 vias
v2: diameter 14, hole 6, Layer 1 - Top Layer to Layer 6 - Bottom Layer, tented both sides, 46 vias
v3: diameter 19.68, hole 7.87, Layer 1 - Top Layer to Layer 6 - Bottom Layer, tented both sides, 7 vias
v4: diameter 20, hole 10, Layer 1 - Top Layer to Layer 6 - Bottom Layer, 2 vias

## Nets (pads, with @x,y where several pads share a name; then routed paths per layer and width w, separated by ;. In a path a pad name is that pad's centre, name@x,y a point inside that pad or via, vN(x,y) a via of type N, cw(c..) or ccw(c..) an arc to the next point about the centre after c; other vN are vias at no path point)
1V5: C4.1 L5.1 R14.2 U2.5 | length 577.7
  Layer 6 - Bottom Layer w15: v1(170,785) 170,725 196.38,698.62 L5.1@230,698.62 ; v1(198,785) 250,740 353,740 370,757 488,757 495,750 495,717 533,679 R14.2@533,642.69
1V8: C7.1 C14.1 C17.1 C18.1 C26.1 C27.1 C28.1 C33.1 C34.1 C35.1 C36.1 C37.1 L8.1 L9.1 R4.2 R5.2 R6.2 R7.2 R8.2 R17.2 R18.2 R19.2 R20.2 U3.5 U4.A7 U4.B5 U4.C6 U4.D2 U4.D4 U4.D5 U4.G4 U4.H7 U5.11 U5.25 U5.28 Y1.4 | length 1765.8
  Layer 1 - Top Layer w8: C28.1@567,468 585,486 ; 585.47,486.47 U5.11@585.47,515.51 ; U5.28@624.84,704.49 624.84,759.53 C34.1@625.32,760
  Layer 1 - Top Layer w15: v1(290,710) R18.2@315.31,710 R19.2@315.31,680 ; v1(300,782) 329.44,782 R6.2@332.44,785 ; R5.2@492.56,790 R5.2@487.56,785 490.56,782 v1(523,782) ; C27.1@526.46,462 v2(541,462) C28.1@557.68,462 ; U5.25@687,704.49 724.49,704.49 750,730 750,759.68 C37.1@750.32,760
  Layer 3 - Signal w15: v1(357,556) 381,580 485,580 541,524 v2(541,462)
  Layer 6 - Bottom Layer w5: U4.H7@495.02,264.98 507.04,277 549.56,277 U4.G4@572.98,300.42 ; U4.C6@521.01,442.15 540.86,462 v2(541,462) 546.99,467.99 U4.B5@546.99,477.58
  Layer 6 - Bottom Layer w8: R20.2@484.69,590 484.69,568.31 495.02,557.98 U4.A7@495.02,513.02 ; U4.H7@495.02,264.98 495.02,249.98 510,235 C14.1@510,218.62 ; U4.D5@546.99,406.72 U4.D4@572.98,406.72 589.69,390 608.23,390 U4.D2@624.94,406.72 643.23,425 695,425 706,414
  Layer 6 - Bottom Layer w12: v1(290,710) 367.43,710 372.43,705 459,705 466.5,697.5 L8.1@466.5,670 470,666.5 470,634 484,620 C17.1@484.68,620 R20.2@484.69,590
  Layer 6 - Bottom Layer w15: 706,414 713,407 713,392 720,385 C18.1@740.32,385 740.32,402.32 751,413 v1(865,413)
  Layer 6 - Bottom Layer w20: v1(494,186) C14.1@510.32,215 ; 600,77 600,105 R8.2@600,120.31 ; 602,74 v1@610,66 ; L9.1@825,541.5 828.5,545 v1(888,545)
  other v1: 612,65 815,305 357,531 888,575 600,760 725,760 600,782 725,782
3V3: L6.1 L7.1 R2.1 U2.1 U2.3 U3.1 U3.3 | length 116.9
  Layer 6 - Bottom Layer w15: v1(175,475) 238.62,475 L7.1@240,476.38
  Layer 6 - Bottom Layer w20: v1(175,430) L6.1@226.38,430
3V3_PG: R20.1 U1.8 U5.9 | length 607.3
  Layer 1 - Top Layer w8: U1.8@332.4,224.53 v1(332.4,245) ; v2(475,545) 504.49,515.51 U5.9@546.1,515.51
  Layer 4 - Signal w5: v1(332.4,245) 332.4,297.6 300,330 300,360 385,445 385,545 394,554 466,554 v2(475,545)
  Layer 6 - Bottom Layer w8: R20.1@445,590 460,575 460,560 v2(475,545)
CAM_SCL: R5.1 U4.F4 U5.4 | length 2189
  Layer 1 - Top Layer w8: R5.1@432.44,785 425,777.56 v4(425,730) 425,691 496.16,619.84 U5.4@520.51,619.84
  Layer 3 - Signal w5: v4(425,730) 425,745 415,755 210,755 153,698 153,537 205,485 205,395 160,350 160,70 200,30 695,30 740,75 v2(740,105)
  Layer 6 - Bottom Layer w5: U4.F4@572.98,335.85 580.15,335.85 602,314 661,314 670,305 670,280 740,210 v2(740,105)
CAM_SDA: R6.1 U4.G3 U5.5 | length 1925.1
  Layer 1 - Top Layer w8: R6.1@387.56,785 395,777.56 v4(395,730) 395,715 407.5,702.5 407.5,687.5 494.84,600.16 U5.5@520.51,600.16
  Layer 3 - Signal w5: v4(395,730) 385,740 215,740 166,691 166,549 220,495 220,390 175,345 175,80 210,45 635,45 v1(645,55)
  Layer 6 - Bottom Layer w5: U4.G3@598.96,300.42 585,286.46 585,245 630,200 630,70 v1(645,55)
D0: U4.G7 U5.19 | length 511.9
  Layer 1 - Top Layer w8: U5.19@709.49,580.47 v2(735,580.47)
  Layer 4 - Signal w5: v2(509.02,314.41) 526.61,332 545,332 557,344 707,344 745,382 745,570.47 v2(735,580.47)
  Layer 6 - Bottom Layer w5: U4.G7@495.02,300.42 v2(509.02,314.41)
D1: U4.G6 U5.20 | length 550.6
  Layer 1 - Top Layer w8: U5.20@709.49,600.16 v2(735,600.16)
  Layer 4 - Signal w5: v2(535,314.41) 560.41,289 669,289 755,375 755,590 745,600 ; v2(735,600.16) 745,600.16
  Layer 6 - Bottom Layer w5: U4.G6@521.01,300.42 v2(535,314.41)
D2: U4.D9 U5.21 | length 779.6
  Layer 1 - Top Layer w8: U5.21@709.49,619.84 v2(735,619.84)
  Layer 4 - Signal w5: v2(429.06,392.72) 420,383.66 420,345 487,278 674,278 765,369 765,605 750.16,619.84 ; v2(735,619.84) 750.16,619.84 ; 750,620 750.16,619.84
  Layer 6 - Bottom Layer w5: v2(429.06,392.72) U4.D9@443.06,406.72
D3: U4.D10 U5.22 | length 876.5
  Layer 1 - Top Layer w8: U5.22@709.49,639.53 v2(735,639.53)
  Layer 4 - Signal w5: v2(403.08,392.72) 403.08,347.78 483.86,267 679,267 815,403 815,585 760.47,639.53 v2(735,639.53)
  Layer 6 - Bottom Layer w5: v2(403.08,392.72) U4.D10@417.07,406.72
D4: U4.D7 U5.23 | length 1063
  Layer 1 - Top Layer w8: U5.23@709.49,659.21 v2(735,659.21)
  Layer 4 - Signal w5: v2(474,425) 405,425 385,405 385,350.86 479.86,256 684,256 827,399 827,593 760.79,659.21 v2(735,659.21)
  Layer 6 - Bottom Layer w5: v2(474,425) 481,418 481,412 486.28,406.72 U4.D7@495.02,406.72
D5: U4.E7 U5.24 | length 1237.5
  Layer 1 - Top Layer w8: U5.24@709.49,678.9 v2(735,678.9)
  Layer 4 - Signal w5: v2(515,391.26) 515,435 505,445 470,445 462,437 397,437 370,410 370,350.86 475.86,245 689,245 839,395 839,601 761.1,678.9 v2(735,678.9)
  Layer 6 - Bottom Layer w5: U4.E7@495.02,371.28 v2(515,391.26)
D6: U4.E9 U5.26 | length 1044.8
  Layer 1 - Top Layer w8: U5.26@664.21,704.49 v2(664.21,730)
  Layer 3 - Signal w5: v2(457.05,385.28) 440,368.23 440,309 467,282 660,282 832,454 832,718 814,736 670.21,736 v2(664.21,730)
  Layer 6 - Bottom Layer w5: U4.E9@443.06,371.28 v2(457.05,385.28)
D7: U4.E8 U5.27 | length 1009.6
  Layer 1 - Top Layer w8: U5.27@644.53,704.49 v2(644.53,730)
  Layer 3 - Signal w5: v2(483.03,385.28) 483.03,348.03 465,330 465,305 475,295 655,295 820,460 820,712 809,723 699,723 688,712 654,712 644.53,721.47 v2(644.53,730)
  Layer 6 - Bottom Layer w5: U4.E8@469.04,371.28 v2(483.03,385.28)
D8: U4.F6 U5.29 | length 761.1
  Layer 1 - Top Layer w8: U5.29@605.16,704.49 v2(605.16,730)
  Layer 3 - Signal w5: v2(535,349.84) 692.84,349.84 765,422 765,694 748,711 704,711 693,700 651,700 621,730 v2(605.16,730)
  Layer 6 - Bottom Layer w5: U4.F6@521.01,335.85 v2(535,349.84)
D9: U4.F7 U5.30 | length 779.9
  Layer 1 - Top Layer w8: U5.30@585.47,704.49 v2(585.47,730)
  Layer 3 - Signal w5: v2(509.02,349.84) 527.17,368 693,368 752,427 752,690 743,699 709,699 700,690 646,690 626,710 595,710 585.47,719.53 v2(585.47,730)
  Layer 6 - Bottom Layer w5: U4.F7@495.02,335.85 v2(509.02,349.84)
D10: U4.F9 U5.31 | length 820
  Layer 1 - Top Layer w8: U5.31@565.79,704.49 v2(565.79,730)
  Layer 4 - Signal w5: v2(457.05,349.84) 485.84,349.84 501,365 550,365 561,354 700,354 735,389 735,545 715,565 715,673 678,710 575,710 565.79,719.21 v2(565.79,730)
  Layer 6 - Bottom Layer w5: U4.F9@443.06,335.85 v2(457.05,349.84)
D11: U4.F8 U5.32 | length 901.2
  Layer 1 - Top Layer w8: U5.32@546.1,704.49 v2(546.1,730)
  Layer 4 - Signal w5: v2(483.99,321.01) 458.13,321.01 438,341.14 438,360 445,367 488.86,367 496.86,375 557,375 567,365 694,365 725,396 725,538 703,560 703,667 672,698 562,698 546.1,713.9 v2(546.1,730)
  Layer 6 - Bottom Layer w5: U4.F8@470,335 v2(483.99,321.01)
DOUT+: C25.2 U5.13 | length 58
  Layer 1 - Top Layer w8: C25.2@624.84,464.84 U5.13@624.84,515.51
  Layer 1 - Top Layer w10: C25.2@624.84,464.84 C25.2@630,459.69
DOUT-: C29.2 U5.12 | length 58
  Layer 1 - Top Layer w8: C29.2@600,459.69 605.16,464.84 U5.12@605.16,515.51
DOUT_N: C29.1 R15.1 | length 29
  Layer 1 - Top Layer w20: R15.1@600,390 C29.1@600,419
DOUT_P: C25.1 L1.2 P1.1 | length 408.4
  Layer 1 - Top Layer w20: C25.1@630,420.32 630,405 670,365 694.54,365 L1.2@762.27,297.27 ; L1.2@767.27,297.27 767.27,162.73 P1.1@825,105
FSIN: U4.F3 U5.15 | length 2276.1
  Layer 1 - Top Layer w8: U5.15@664.21,515.51 664.21,499.79 v2(674,490)
  Layer 3 - Signal w5: v2(674,490) 610,490 430,670 230,670 193,633 193,567 250,510 250,380 205,335 205,140 230,115 355,115 380,90 450,90 475,115 475,195 520,240 755,240 805,190 v2(850,190)
  Layer 6 - Bottom Layer w5: U4.F3@598.96,335.85 611.11,348 687,348 700,335 700,295 805,190 v2(850,190)
GND: C1.2 C2.2 C3.2 C4.2 C5.2 C6.2 C7.2 C8.2 C9.2 C10.2 C11.2 C12.2 C13.2 C14.2 C15.2 C16.2 C17.2 C18.2 C19.2 C20.2 C21.2 C22.2 C23.2 C24.2 C26.2 C27.2 C28.2 C30.2 C31.2 C32.2 C33.2 C34.2 C35.2 C36.2 C37.2 P1.2 P1.3 P1.4 P1.5 R10.1 R11.1 R12.1 R13.1 R15.2 R21.1 R22.1 U1.1 U1.4 U1.5 U1.9 U2.2 U3.2 U4.A1 U4.A2 U4.A3 U4.A4 U4.A9 U4.A10 U4.B1 U4.B2 U4.B9 U4.B10 U4.C3 U4.C4 U4.C9 U4.D1 U4.D3 U4.E2 U4.E10 U4.F10 U4.G1 U4.G2 U4.G9 U4.G10 U4.H1 U4.H2 U4.H3 U4.H4 U4.H5 U4.H9 U4.H10 U5.7 U5.33 Y1.2 | length 1919.1
  Layer 1 - Top Layer w8: U5.7@520.51,560.79 592.43,560.79 U5.33@628.32,596.68
  Layer 1 - Top Layer w10: C3.2@218.31,719 218.31,735.69 C4.2@231.62,758 ; U1.9@305.47,165.47 U1.5@332.4,165.47
  Layer 1 - Top Layer w15: U2.2@220,575.87 v1(220,610) ; v1(257,785) 231.62,758 297.32,758 R21.1@315.32,740 ; R22.1@315.32,650 293,627.68 v1(293,612) 301.38,603.62 C7.2@330,603.62 357.54,603.62 C23.2@388.08,573.08 410.08,551.08 C24.2@410.08,550.08 410.08,545.99 v2(429.06,527.01) v2(429.06,491.57) ; v1(790,510) 810,510 820.31,520.31 C35.2@820.31,545 ; C30.2@821.58,367.42 C30.2@832.58,367.42
  Layer 1 - Top Layer w20: U3.2@220.87,470 v1(279,470) 372.44,470 C26.2@390,452.44 393.7,456.14 v2(429.06,456.14) ; C27.2@525,421.31 560,421.31 C28.2@560,420.31 560,385.69 R15.2@559.31,385 ; Y1.2@774.57,652.56 774.57,680 784.57,690 v1(795,690)
  Layer 6 - Bottom Layer w5: v2(429.06,456.14) U4.C9@443.06,442.15 ; v2(429.06,491.57) U4.B9@443.06,477.58 ; v2(429.06,527.01) U4.A9@443.06,513.02
  Layer 6 - Bottom Layer w8: v2(541,424) 554.83,424 U4.C4@572.98,442.15 U4.C3@598.96,442.15 U4.D3@598.96,406.72 ; U4.E2@624.94,371.28 624.94,380.73 U4.D1@650.93,406.72 673.28,406.72 v1(685,395)
  Layer 6 - Bottom Layer w10: v2@380,615 415,615 420,620 C17.2@445.31,620
  Layer 6 - Bottom Layer w15: v1(220,610) 227.44,602.56 C12.2@227.44,575 ; v1(279,470) C21.2@315.31,470 ; C22.2@287.44,670 287.44,617.56 v1(293,612) 302,612 319.69,629.69 C10.2@325,629.69 C11.2@355,629.69 ; R12.1@360,280.32 409.68,280.32 ; C8.2@749.69,545 749.69,507.87 C20.2@750,507.56 ; C20.2@750,511.5 751.5,510 v1(790,510) ; v1(770,70) R11.1@770,95.32 ; R13.1@779.68,355 840,355 v1(860,335) ; C18.2@779.69,385 850,385 v1(880,355) ; R10.1@834.68,165 v1(860,165)
  other v1: 295,93 321,93 685,155 715,155 715,185 545,190 450,241 230,250 230,280 230,310 260,310 290,310 690,760 815,760 690,782 815,782
  other v2: 379.43,615.57
  other v3: 295,179.25 295,210.75 615,560 565,610 615,610 665,610 615,660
